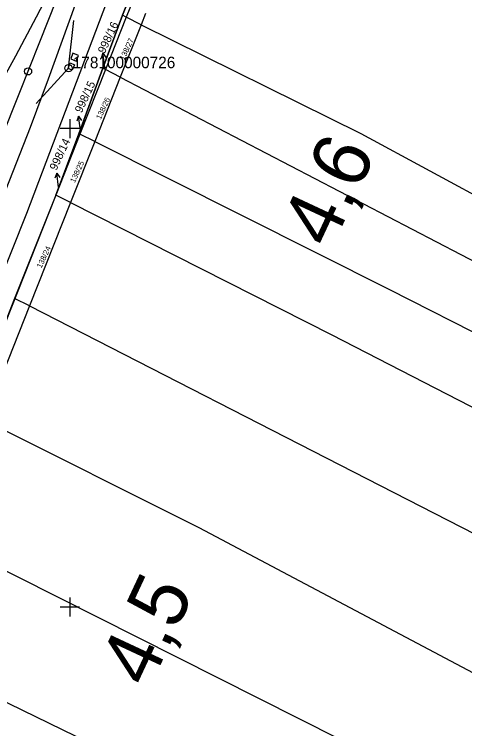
# Model space of a CAD drawing. Extents: x -755344 to -754412, y -1162670 to -1161477.
# Drawn here: x -754811.6 to -754717.5, y -1162225.4 to -1162076.1 of the extents above; entities that cross this region are included whole.
import ezdxf

# ---------------------------------------------------------------- set-up
doc = ezdxf.new("R2010")
doc.units = 0
for name, color, linetype in [('Body ŽBP', 7, 'Continuous'), ('Katastrální hranice', 7, 'Continuous'), ('Staniceni a namezniky', 7, 'Continuous'), ('Síť', 7, 'Continuous'), ('Vrstva 1', 7, 'Continuous'), ('Vrstva 12', 7, 'Continuous'), ('Vrstva 53', 7, 'Continuous'), ('Vrstva 55', 7, 'Continuous'), ('Vrstva 57', 7, 'Continuous')]:
    doc.layers.add(name, color=color, linetype=linetype)

msp = doc.modelspace()

# ---------------------------------------------------------------- linework, layer by layer
at = {"layer": 'Body ŽBP'}
for p, q in [((-754800.27, -1162087.38), (-754799.19, -1162077.44)), ((-754800.27, -1162087.38), (-754807.05, -1162094.74)), ((-754800.25, -1162087.33), (-754800.29, -1162087.43)), ((-754800.27, -1162087.38), (-754800.27, -1162087.38))]:
    msp.add_line(p, q, dxfattribs=at)
msp.add_circle((-754800.27, -1162087.38), 0.756, dxfattribs=at)
at = {"layer": 'Katastrální hranice'}
for p, q in [((-754783.47, -1162064.75), (-754788.22, -1162076.73)), ((-754788.22, -1162076.73), (-754792.54, -1162087.63)), ((-754792.54, -1162087.63), (-754797.91, -1162101.16)), ((-754797.91, -1162101.16), (-754802.96, -1162113.9)), ((-754802.96, -1162113.9), (-754811.54, -1162135.54)), ((-754811.54, -1162135.54), (-754816.22, -1162147.35))]:
    msp.add_line(p, q, dxfattribs=at)
at = {"layer": 'Staniceni a namezniky'}
msp.add_circle((-754808.73, -1162088.04), 0.75, dxfattribs=at)
at = {"layer": 'Síť'}
for points in [[(-754800, -1162098), (-754800, -1162100), (-754800, -1162102)], [(-754798, -1162100), (-754800, -1162100), (-754802, -1162100)], [(-754800, -1162198), (-754800, -1162200), (-754800, -1162202)], [(-754798, -1162200), (-754800, -1162200), (-754802, -1162200)]]:
    msp.add_lwpolyline(points, dxfattribs=at)
at = {"layer": 'Vrstva 1'}
for points in [[(-754814.09, -1162114.62), (-754808.25, -1162099.68), (-754804.47, -1162089.62), (-754798.9, -1162074.23), (-754793.63, -1162059.04), (-754788.99, -1162045.27)], [(-754802.82, -1162068.46), (-754807.01, -1162076.73), (-754811.35, -1162084.87), (-754815.39, -1162092.12), (-754818.66, -1162097.67), (-754820.65, -1162100.99), (-754825.85, -1162109.19), (-754831.64, -1162117.68), (-754836.49, -1162124.37), (-754839.8, -1162128.71), (-754840.46, -1162129.57), (-754840.79, -1162129.99), (-754847.19, -1162138.25), (-754849.01, -1162140.58), (-754849.98, -1162141.84), (-754854.92, -1162148.19), (-754860.18, -1162155.01)], [(-754855.13, -1162205.06), (-754851.41, -1162195.67), (-754847.87, -1162186.72), (-754844.23, -1162177.57), (-754840.47, -1162168.07), (-754836.48, -1162158.01), (-754832.73, -1162148.55), (-754829.03, -1162139.24), (-754824.91, -1162128.83), (-754821.22, -1162119.52), (-754818.37, -1162112.34), (-754814.26, -1162101.97), (-754810.6, -1162092.76), (-754806.3, -1162081.9), (-754802.77, -1162073.01), (-754801.21, -1162069.06)]]:
    msp.add_lwpolyline(points, dxfattribs=at)
at = {"layer": 'Vrstva 12'}
for points in [[(-754799.79, -1162085.43), (-754798.65, -1162085.92), (-754798.16, -1162084.75), (-754799.39, -1162084.21), (-754799.79, -1162085.43)], [(-754800.38, -1162087.44), (-754799.92, -1162086.29), (-754799, -1162086.68), (-754799.48, -1162087.82), (-754800.38, -1162087.44)]]:
    msp.add_lwpolyline(points, dxfattribs=at)
at = {"layer": 'Vrstva 53'}
msp.add_lwpolyline([(-754717.5, -1161955.11), (-754731.42, -1161979.09), (-754747.41, -1161959.83), (-754749.74, -1161970.12), (-754750.32, -1161972.64), (-754745.89, -1161978.47), (-754747.84, -1161978.77), (-754754.27, -1161988.55), (-754756.33, -1161996.85), (-754760.29, -1162004.33), (-754789, -1162076.26), (-754793.13, -1162087.4), (-754798.15, -1162101.07), (-754802.96, -1162113.9), (-754816.22, -1162147.35), (-754851.45, -1162231.96), (-754887.61, -1162319.28)], dxfattribs=at)
at = {"layer": 'Vrstva 55'}
for p, q in [((-754783.47, -1162064.75), (-754788.22, -1162076.73)), ((-754783.47, -1162064.75), (-754788.22, -1162076.73)), ((-754793.13, -1162087.4), (-754789, -1162076.26)), ((-754788.22, -1162076.73), (-754792.54, -1162087.63)), ((-754788.22, -1162076.73), (-754792.54, -1162087.63)), ((-754788.22, -1162076.73), (-754789, -1162076.26)), ((-754785.12, -1162078.33), (-754788.22, -1162076.73)), ((-754784.18, -1162075.95), (-754785.12, -1162078.33)), ((-754785.12, -1162078.33), (-754789.45, -1162089.23)), ((-754798.15, -1162101.07), (-754793.13, -1162087.4)), ((-754792.54, -1162087.63), (-754793.13, -1162087.4)), ((-754792.54, -1162087.63), (-754797.91, -1162101.16)), ((-754792.54, -1162087.63), (-754797.91, -1162101.16)), ((-754789.45, -1162089.23), (-754792.54, -1162087.63)), ((-754789.45, -1162089.23), (-754794.8, -1162102.72)), ((-754802.96, -1162113.9), (-754798.15, -1162101.07)), ((-754797.91, -1162101.16), (-754802.96, -1162113.9)), ((-754797.91, -1162101.16), (-754802.96, -1162113.9)), ((-754797.91, -1162101.16), (-754798.15, -1162101.07)), ((-754794.8, -1162102.72), (-754797.91, -1162101.16)), ((-754794.8, -1162102.72), (-754799.86, -1162115.47)), ((-754802.96, -1162113.9), (-754811.54, -1162135.54)), ((-754802.96, -1162113.9), (-754811.54, -1162135.54)), ((-754799.86, -1162115.47), (-754802.96, -1162113.9)), ((-754799.86, -1162115.47), (-754808.43, -1162137.05)), ((-754811.54, -1162135.54), (-754816.22, -1162147.35)), ((-754811.54, -1162135.54), (-754816.22, -1162147.35)), ((-754808.43, -1162137.05), (-754811.54, -1162135.54)), ((-754808.43, -1162137.05), (-754817.91, -1162160.94))]:
    msp.add_line(p, q, dxfattribs=at)
for points in [[(-754978.01, -1162551.88), (-754981.37, -1162542.41), (-754930.02, -1162407.36), (-754870.17, -1162267.96), (-754836.4, -1162183.6), (-754824.89, -1162157.4), (-754808.97, -1162117.64), (-754790.52, -1162068.93), (-754761.32, -1161999.17), (-754754.27, -1161988.55)], [(-754789, -1162076.26), (-754760.29, -1162004.33), (-754756.33, -1161996.85)], [(-754785.12, -1162078.33), (-754739.17, -1162101.03), (-754695.9, -1162124.41), (-754654.4, -1162147.91), (-754627.49, -1162162.07)], [(-754789.45, -1162089.23), (-754713.23, -1162128.96), (-754644.57, -1162165.98), (-754632.53, -1162173.22)], [(-754794.8, -1162102.72), (-754733.16, -1162133.64), (-754689.89, -1162155.62), (-754637.42, -1162185.04)], [(-754799.86, -1162115.47), (-754745.23, -1162143.07), (-754649.07, -1162192.57), (-754628.02, -1162204.3)], [(-754808.43, -1162137.05), (-754656.15, -1162215.06), (-754622.57, -1162236.02)], [(-754817.91, -1162160.94), (-754773.06, -1162183.36), (-754661.89, -1162242.23), (-754631.58, -1162259.43)], [(-754827.93, -1162185.11), (-754743.71, -1162227.55), (-754668.64, -1162267.68), (-754640.75, -1162283.26)], [(-754837.67, -1162208.02), (-754737.97, -1162256.6), (-754682.13, -1162286.58), (-754649.24, -1162305.33)]]:
    msp.add_lwpolyline(points, dxfattribs=at)
at = {"layer": 'Vrstva 57'}
for p, q in [((-754793.08, -1162084.2), (-754793.45, -1162085.25)), ((-754792.69, -1162087.17), (-754793.08, -1162084.2)), ((-754793.08, -1162084.2), (-754792.46, -1162085.12)), ((-754798.16, -1162097.38), (-754798.52, -1162098.44)), ((-754797.77, -1162100.36), (-754798.16, -1162097.38)), ((-754798.16, -1162097.38), (-754797.53, -1162098.31)), ((-754802.74, -1162109.29), (-754803.11, -1162110.34)), ((-754802.35, -1162112.26), (-754802.74, -1162109.29)), ((-754802.74, -1162109.29), (-754802.11, -1162110.22))]:
    msp.add_line(p, q, dxfattribs=at)

# ---------------------------------------------------------------- texts
at = {"layer": 'Body ŽBP'}
msp.add_text(' 178100000726', height=2.4, dxfattribs=at).set_placement((-754800.27, -1162087.38))
at = {"layer": 'Staniceni a namezniky'}
for s, p in [('4,6', (-754745.4, -1162125.39)), ('4,5', (-754783.42, -1162217.2))]:
    msp.add_text(s, height=12, rotation=64.9752, dxfattribs=at).set_placement(p)
at = {"layer": 'Vrstva 57'}
for s, height, p in [('998/16', 1.7, (-754792.72, -1162084.46)), ('138/27', 1.139, (-754788.63, -1162085.8)), ('998/15', 1.7, (-754797.54, -1162096.87)), ('138/26', 1.139, (-754793.55, -1162098.19)), ('998/14', 1.7, (-754802.81, -1162108.87)), ('138/25', 1.139, (-754798.97, -1162111.43)), ('138/24', 1.139, (-754805.94, -1162129.27))]:
    msp.add_text(s, height=height, rotation=65, dxfattribs=at).set_placement(p)

doc.saveas('drawing.dxf')
